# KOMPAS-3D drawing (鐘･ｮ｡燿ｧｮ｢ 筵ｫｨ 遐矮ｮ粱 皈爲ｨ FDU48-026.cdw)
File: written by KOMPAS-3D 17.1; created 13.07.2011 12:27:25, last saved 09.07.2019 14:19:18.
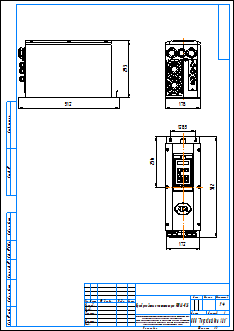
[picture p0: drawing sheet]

Sheet 1: A3, portrait

Title block, sheet 1: name: Преобразователи частоты серии FDU48-026; scale: 1:4; sheets: 1; sheet format: A3; stored path: \\adlc.lan\data\АДЛ_ПКД\3D-модели\Поставщики\Оборудование Emotron\Преобразователи частоты\Серия FDU 2.0\KOMPAS 2D\Преобразователи частоты серии FDU48-026.cdw

Views: Спереди 1
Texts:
  Рама для чертежей
  Лит-Масса-Масштаб
  Материал-Предприятие
  Масштаб
  Изм.
  Лист
  № докум.
  Подп.
  Дата
  Лит.
  Разраб.
  Пров.
  Т.контр.
  Листов
  Внимание! Данный продукт является объектом авторского права ООО «Торговый Дом АДЛ».
  Запрещается изменение, копирование, распространение
  (в том числе путем копирования на другие сайты и ресурсы в Интернете)
  или любое иное использование информации и объектов без предварительного
  согласия правообладателя (ООО «Торговый Дом АДЛ»).
  Н.контр.
  Утв.
  ООО "Торговый дом АДЛ"
  Изменение
  Номер документа
  Подпись
  Обозначение документа
  Наименование изделия
  Масса изделия по ГОСТ 2.109-73
  Порядковый номер листа
  Общее количество листов в документе
  Характер работы, выполненной лицом, подписавшим документ
  Наименование или индекс предприятия, выпускающего документ
  Инв. № подл.
  Подп. и дата
  Взам. инв. №
  Инв. № дубл.
  Инвентарный номер подлинника по ГОСТ 2.501-68
  Подпись принявшего подлинник в отдел технической документации
  Инвентарный номер подлинника, взамен которого выпущен данный подлинник
  Инвентарный номер дубликата по ГОСТ 2.502-68
  Подпись принявшего дубликат в отдел технической документации
  Справ. №
  Перв. примен.
  Обозначение документа, взамен или на основании которого выпущен данный документ
  Обозначение документа, в котором впервые записан данный документ
  Подпись лица, копировавшего чертеж
  Обозначение формата листа
  !Рама для чертежа
Dimensions and other numbers on the sheet: 178; 512; 128,5; 172; 293; 256; 1:4; 1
